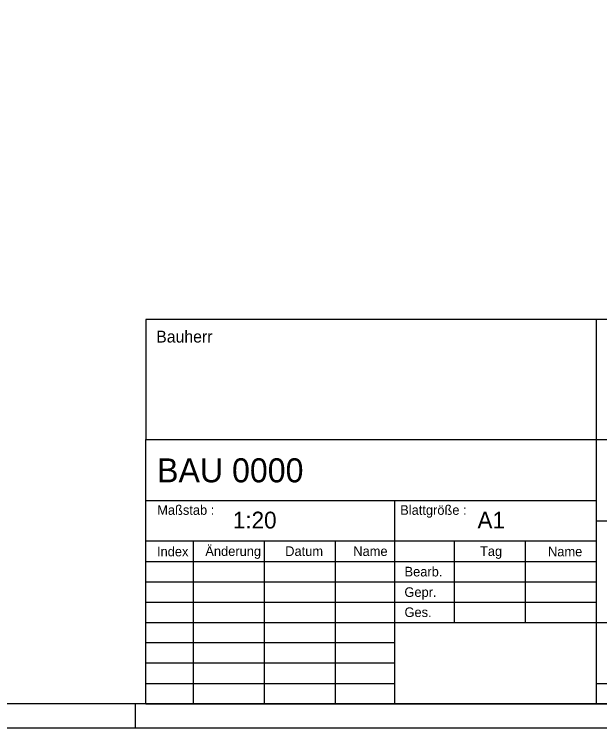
# Model space of a CAD drawing. Extents: x 0 to 16.8, y 0 to 11.9.
# Drawn here: x 12.615 to 15.053, y 0 to 2.97 of the extents above; entities that cross this region are included whole.
import ezdxf

# ---------------------------------------------------------------- set-up
doc = ezdxf.new("R2010")
doc.units = 0
doc.layers.add('90_Plankopf', color=7, linetype='Continuous')

msp = doc.modelspace()

# ---------------------------------------------------------------- linework, layer by layer
at = {"layer": '90_Plankopf'}
for p, q in [((16.72, 1.6998), (13.1624, 1.6998)), ((13.1624, 1.6998), (13.1624, 1.1998)), ((15.04, 1.1998), (15.04, 1.6998)), ((13.1624, 1.1998), (16.72, 1.1998)), ((13.1624, 0.1), (13.1624, 1.1998)), ((13.1624, 1.1998), (16.72, 1.1998)), ((15.04, 0.1), (15.04, 1.1998)), ((13.1624, 0.946), (15.04, 0.946)), ((14.2, 0.1), (14.2, 0.946)), ((15.04, 0.8614), (16.72, 0.8614)), ((13.1624, 0.7774), (15.04, 0.7774)), ((13.36, 0.7768), (13.36, 0.1)), ((13.6565, 0.1), (13.6565, 0.7768)), ((13.953, 0.1), (13.953, 0.7768)), ((14.4471, 0.7768), (14.4471, 0.4384)), ((14.7436, 0.4384), (14.7436, 0.7768)), ((13.1624, 0.6926), (15.04, 0.6926)), ((13.1624, 0.6076), (15.04, 0.6076)), ((13.1624, 0.523), (15.04, 0.523)), ((13.1624, 0.4384), (15.04, 0.4384)), ((13.1624, 0.4384), (15.04, 0.4384)), ((14.2, 0.4384), (15.04, 0.4384)), ((15.04, 0.4384), (16.72, 0.4384)), ((14.2, 0.3538), (13.1624, 0.3538)), ((14.2, 0.2692), (13.1624, 0.2692)), ((13.1624, 0.1846), (14.2, 0.1846)), ((15.04, 0.1846), (16.72, 0.1846)), ((13.12, 0), (13.12, 0.1)), ((16.72, 0.1), (13.1624, 0.1)), ((13.1624, 0.1), (14.2, 0.1)), ((13.396, 0.1), (16.72, 0.1)), ((13.396, 0.1), (16.72, 0.1))]:
    msp.add_line(p, q, dxfattribs=at)
for points in [[(0, 0), (16.82, 0), (16.82, 11.88), (0, 11.88)], [(0.5, 11.78), (16.72, 11.78), (16.72, 0.1), (0.5, 0.1)]]:
    msp.add_lwpolyline(points, close=True, dxfattribs=at)

# ---------------------------------------------------------------- texts
for s, height, p in [('Bauherr', 0.04927, (13.2061, 1.6035)), ('BAU 0000      ', 0.1, (13.2098, 1.0215)), ('Maßstab :', 0.04, (13.2103, 0.8863)), ('Blattgröße :', 0.039998, (14.2223, 0.8863)), ('1:20     ', 0.07, (13.5252, 0.8294)), ('A1       ', 0.07, (14.544, 0.8294)), ('Index', 0.04, (13.2094, 0.7135)), ('Änderung', 0.04, (13.4107, 0.715)), ('Datum', 0.04, (13.7434, 0.715)), ('Name', 0.04, (14.0269, 0.715)), ('Tag', 0.04, (14.5545, 0.715)), ('Name', 0.04, (14.8378, 0.7135)), ('Bearb.', 0.04, (14.2403, 0.6298)), ('Gepr.', 0.04, (14.2398, 0.5446)), ('Ges.', 0.04, (14.2401, 0.4609))]:
    msp.add_text(s, height=height, dxfattribs=at).set_placement(p)

doc.saveas('drawing.dxf')
